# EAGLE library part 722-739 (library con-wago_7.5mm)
Serie 722, Federleiste mit geraden Einlötstiften / Series 722, Female connector with straight solder pins Polzahl / Pole No.: 9 Rastermaß / Pitch: 7.5 mm Bemessungsspannung / Rated Voltage: 630 V Nennstrom / Nominal Current: 12 A Lötstiftlänge: / Solder Pin Length: 5 mm Farbe / Color: lichtgrau / light gray Stand: 01.01.2012. Die jeweils aktuellen Daten zu diesem Artikel finden Sie in unserem Produktkatalog, den Sie unter www.wago.com einsehen können. As of: 01/01/2012. Please find the newest data for this article in our product catalogue, which can be viewed under www.wago.com.
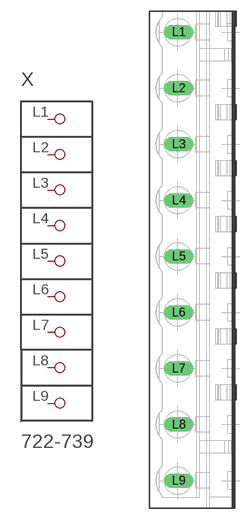
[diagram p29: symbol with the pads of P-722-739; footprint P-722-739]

Designator prefix X

## 722-739  [P-722-739]
L1  P1
L2  P2
L3  P3
L4  P4
L5  P5
L6  P6
L7  P7
L8  P8
L9  P9

## Footprint P-722-739 (pad centres in mm)
drill 1.3 long: L1 -2.092,30.45; L2 -2.092,22.95; L3 -2.092,15.45; L4 -2.092,7.95; L5 -2.092,0.45; L6 -2.092,-7.05; L7 -2.092,-14.55; L8 -2.092,-22.05; L9 -2.092,-29.55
